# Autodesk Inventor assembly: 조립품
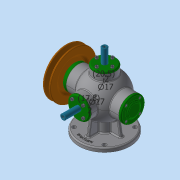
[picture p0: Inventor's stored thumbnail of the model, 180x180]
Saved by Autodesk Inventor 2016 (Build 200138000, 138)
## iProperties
Created: 2019-11
Part Number: 조립품
Material: 일반
Document SubType Name: Assembly
Designer: user
Author: user
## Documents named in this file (17)
- C:\Users\user\Desktop\391120V1003\조립품.iam
- C:\Users\user\Desktop\391120V1003\V-벨트풀리.ipt
- C:\Users\user\Desktop\391120V1003\너트 M8x1.ipt
- C:\Users\user\Desktop\391120V1003\뒤커버.ipt
- C:\Users\user\Desktop\391120V1003\베어링 6202.ipt
- C:\Users\user\Desktop\391120V1003\본체.ipt
- C:\Users\user\Desktop\391120V1003\본체커버.ipt
- C:\Users\user\Desktop\391120V1003\볼트 M4.ipt
- C:\Users\user\Desktop\391120V1003\스프링1.ipt
- C:\Users\user\Desktop\391120V1003\스프링2.ipt
- C:\Users\user\Desktop\391120V1003\슬라이드 커버.ipt
- C:\Users\user\Desktop\391120V1003\슬라이드.ipt
- C:\Users\user\Desktop\391120V1003\앞커버.ipt
- C:\Users\user\Desktop\391120V1003\오일 실.ipt
- C:\Users\user\Desktop\391120V1003\와셔 8x17.ipt
- C:\Users\user\Desktop\391120V1003\축.ipt
- C:\Users\user\Desktop\391120V1003\키 4x4.ipt
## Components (1 placed, 1 different names)
1. V-벨트풀리:1
